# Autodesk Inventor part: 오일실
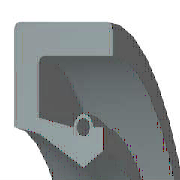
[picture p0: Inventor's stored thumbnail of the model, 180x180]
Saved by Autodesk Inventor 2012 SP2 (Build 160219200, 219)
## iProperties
IsCustomPart: 1
Company: 한국ATC센터
Created: 2014-11
Part Number: 오일실
Material: 고무
Description: 오일-실
Document SubType Name: Modeling
Standard: KS B 2804
Designer: KYOUNG IL JANG
Standards Organization: KS
Language: ko-KR
Size Designation: S - 25 40 8
Categories: <MemberInstance><Categories><Category DisplayName="샤프트 부품" InternalName="7f7aeb1f-a693-4053-b835-cee3144e0d98" Mnemonic="SHFT"><Category DisplayName="실링" Intern
Density: 0.93 g/cm^3
Mass: 2.48215 g
Surface Area: 40.3381 cm^2
Volume: 2.66898 cm^3
Author: KYOUNG IL JANG
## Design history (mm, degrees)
revolve "본체" stored, may be unused: angle "d17" = 90 deg
revolve "스프링1" stored, may be unused: angle "d18" = 90 deg
body "Solid1"
sketch "스케치1"
  geometry: L1 (0, 20)-(8, 20); L2 (8, 20)-(8, 18.75); L3 (8, 18.75)-(1.75, 18.75); L4 (0, 20)-(0, 14.6); L5 (0, 14.6)-(1.75, 14.25); L6 (1.75, 14.25)-(4.9, 12.5); L7 (4.9, 12.5)-(0, 12.5); L8 (6.3, 13.375)-(6.3, 14.6); L9 (0, 0)-(9.586, 0) reference; L10 (4.9, 12.5)-(6.3, 13.375); L11 (0, 18)-(0, -3) reference; L12 (-1.917, 0)-(11.503, 0) reference; L13 (4.2, 14.6)-(1.75, 15.09); L14 (1.75, 15.09)-(1.75, 18.75); L15 (6.3, 14.6)-(5.6, 14.6); C1 r 0.455 at (4.9, 14.6); A1 r 0.7 centre (4.9, 14.6) between (5.6, 14.6) and (4.2, 14.6)
  constraints: 26 end point, 5 horizontal alignment, 4 perpendicular, 2 centre point, 2 collinear, 2 horizontal, 2 parallel, 2 point on circle, 2 point on line, 2 vertical alignment, 1 coincident
  dimensions: "d0" = 40 diameter of L1 L9 (= SD2); "d1" = 26.75 diameter of L8.start L9 (= ABDM); "d2" = 1.25 distance of L1.end L2.end (computed from SD); "d3" = 0.91 diameter of C1 (= SPDI); "d4" = 1.4 diameter of A1 (= SPDA); "d5" = 25 diameter of L6.end L9 (= NND); "d6" = 28.5 diameter of L5.end L9 (= TKDM); "d7" = 29.2 diameter of L4.end L9 (= HLDM); "d8" = 4.9 distance from line of C1.centre L4 (= SPDST); "d9" = 6.3 distance between parallel lines of L8 L4 (= SDI); "d10" = 8 distance between parallel lines of L2 L4 (= SWDT); "d12" = 1.75 distance between parallel lines of L14 L4 (= SD)
fillet "모깎기1" dims "d11" = 0.3 (= RR)
other parameters: "SD2" = 40 [user parameter; used in 1 equation term], "SWDT" = 8 [user parameter; used in 1 equation term], "RR" = 0.3 [user parameter; used in 1 equation term], "SD" = 1.75 [user parameter; used in 2 equation terms], "NND" = 25 [user parameter; used in 1 equation term], "SPDA" = 1.4 [user parameter; used in 1 equation term], "SPDI" = 0.91 [user parameter; used in 1 equation term], "TKDM" = 28.5 [user parameter; used in 1 equation term], "HLDM" = 29.2 [user parameter; used in 1 equation term], "ABDM" = 26.75 [user parameter; used in 1 equation term], "SDI" = 6.3 [user parameter; used in 1 equation term], "SPDST" = 4.9 [user parameter; used in 1 equation term], "d13" = 0, "d14" = 0, "d15" = 0, "LAB" = 0.35 [user parameter]
